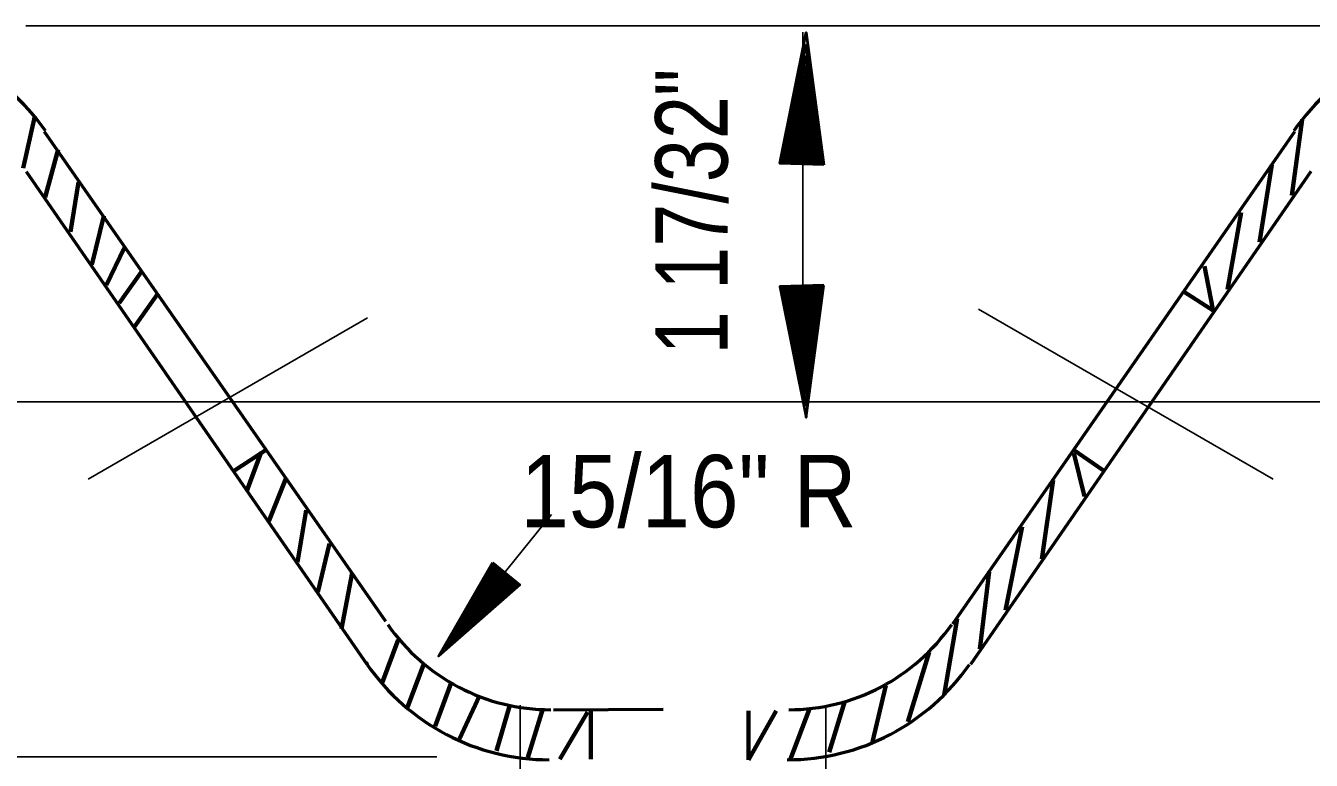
# Model space of a CAD drawing. Extents: x 895.6 to 930.4, y -2278.6 to -2254.7.
# Drawn here: x 901.427 to 903.71, y -2273.45 to -2272.145 of the extents above; entities that cross this region are included whole.
import ezdxf

# ---------------------------------------------------------------- set-up
doc = ezdxf.new("R2010")
doc.units = 0
doc.header["$LTSCALE"] = 0.051
doc.layers.add('1', color=7, linetype='Continuous', lineweight=70)
doc.layers.add('3', color=7, linetype='Continuous', lineweight=40)

msp = doc.modelspace()

# ---------------------------------------------------------------- hatches: boundary and pattern name
at = {"layer": '3'}
for points in [[(902.8445, -2272.3925), (902.7665, -2272.38983), (902.81342, -2272.15717), (902.81342, -2272.15717)], [(902.84058, -2272.39125), (902.77042, -2272.38892), (902.81258, -2272.17958), (902.81258, -2272.17958)], [(902.83708, -2272.39025), (902.774, -2272.38808), (902.812, -2272.19967), (902.812, -2272.19967)], [(902.834, -2272.38925), (902.77725, -2272.38733), (902.81142, -2272.21775), (902.81142, -2272.21775)], [(902.83133, -2272.3885), (902.78017, -2272.38667), (902.81092, -2272.234), (902.81092, -2272.234)], [(902.82867, -2272.3875), (902.78267, -2272.386), (902.81042, -2272.24867), (902.81042, -2272.24867)], [(902.82633, -2272.38692), (902.78492, -2272.38558), (902.80992, -2272.26183), (902.80992, -2272.26183)], [(902.82442, -2272.38617), (902.78708, -2272.38508), (902.80958, -2272.27383), (902.80958, -2272.27383)], [(902.82258, -2272.38583), (902.78892, -2272.3845), (902.80908, -2272.28442), (902.80908, -2272.28442)], [(902.82083, -2272.38517), (902.7905, -2272.38408), (902.80883, -2272.29408), (902.80883, -2272.29408)], [(902.81933, -2272.38467), (902.79217, -2272.38375), (902.8085, -2272.30275), (902.8085, -2272.30275)], [(902.81792, -2272.38433), (902.79358, -2272.38342), (902.80817, -2272.3105), (902.80817, -2272.3105)], [(902.81683, -2272.38383), (902.79475, -2272.38317), (902.808, -2272.31767), (902.808, -2272.31767)], [(902.81567, -2272.38342), (902.79583, -2272.38292), (902.80783, -2272.32375), (902.80783, -2272.32375)], [(902.81475, -2272.38317), (902.79683, -2272.38258), (902.80767, -2272.3295), (902.80767, -2272.3295)], [(902.81383, -2272.38292), (902.79767, -2272.3825), (902.80733, -2272.33458), (902.80733, -2272.33458)], [(902.813, -2272.38267), (902.79842, -2272.38217), (902.80717, -2272.33917), (902.80717, -2272.33917)], [(902.81225, -2272.3825), (902.79925, -2272.38208), (902.80708, -2272.34325), (902.80708, -2272.34325)], [(902.81183, -2272.38217), (902.8, -2272.38192), (902.80708, -2272.34692), (902.80708, -2272.34692)], [(902.81125, -2272.382), (902.80067, -2272.38167), (902.807, -2272.35017), (902.807, -2272.35017)], [(902.81092, -2272.38175), (902.80133, -2272.38142), (902.80717, -2272.35317), (902.80717, -2272.35317)], [(902.81033, -2272.38175), (902.80183, -2272.38142), (902.807, -2272.35592), (902.807, -2272.35592)], [(902.80983, -2272.38158), (902.80225, -2272.38125), (902.80675, -2272.35833), (902.80675, -2272.35833)], [(902.80958, -2272.38142), (902.80275, -2272.38117), (902.80683, -2272.3605), (902.80683, -2272.3605)], [(902.8445, -2272.60583), (902.7665, -2272.6085), (902.81342, -2272.84117), (902.81342, -2272.84117)], [(902.84058, -2272.60708), (902.77042, -2272.60942), (902.81258, -2272.81875), (902.81258, -2272.81875)], [(902.83708, -2272.60808), (902.774, -2272.61025), (902.812, -2272.79867), (902.812, -2272.79867)], [(902.834, -2272.60908), (902.77725, -2272.611), (902.81142, -2272.78058), (902.81142, -2272.78058)], [(902.83133, -2272.60983), (902.78017, -2272.61167), (902.81092, -2272.76433), (902.81092, -2272.76433)], [(902.82867, -2272.61083), (902.78267, -2272.61233), (902.81042, -2272.74967), (902.81042, -2272.74967)], [(902.82633, -2272.61142), (902.78492, -2272.61275), (902.80992, -2272.7365), (902.80992, -2272.7365)], [(902.82442, -2272.61217), (902.78708, -2272.61325), (902.80958, -2272.7245), (902.80958, -2272.7245)], [(902.82258, -2272.6125), (902.78892, -2272.61383), (902.80908, -2272.71392), (902.80908, -2272.71392)], [(902.82083, -2272.61317), (902.7905, -2272.61425), (902.80883, -2272.70425), (902.80883, -2272.70425)], [(902.81933, -2272.61367), (902.79217, -2272.61458), (902.8085, -2272.69558), (902.8085, -2272.69558)], [(902.81792, -2272.614), (902.79358, -2272.61492), (902.80817, -2272.68783), (902.80817, -2272.68783)], [(902.81683, -2272.6145), (902.79475, -2272.61517), (902.808, -2272.68067), (902.808, -2272.68067)], [(902.81567, -2272.61492), (902.79583, -2272.61542), (902.80783, -2272.67458), (902.80783, -2272.67458)], [(902.81475, -2272.61517), (902.79683, -2272.61575), (902.80767, -2272.66883), (902.80767, -2272.66883)], [(902.81383, -2272.61542), (902.79767, -2272.61583), (902.80733, -2272.66375), (902.80733, -2272.66375)], [(902.813, -2272.61567), (902.79842, -2272.61617), (902.80717, -2272.65917), (902.80717, -2272.65917)], [(902.81225, -2272.61583), (902.79925, -2272.61625), (902.80708, -2272.65508), (902.80708, -2272.65508)], [(902.81183, -2272.61617), (902.8, -2272.61642), (902.80708, -2272.65142), (902.80708, -2272.65142)], [(902.81125, -2272.61633), (902.80067, -2272.61667), (902.807, -2272.64817), (902.807, -2272.64817)], [(902.81092, -2272.61658), (902.80133, -2272.61692), (902.80717, -2272.64517), (902.80717, -2272.64517)], [(902.81033, -2272.61658), (902.80183, -2272.61692), (902.807, -2272.64242), (902.807, -2272.64242)], [(902.80983, -2272.61675), (902.80225, -2272.61708), (902.80675, -2272.64), (902.80675, -2272.64)], [(902.80958, -2272.61692), (902.80275, -2272.61717), (902.80683, -2272.63783), (902.80683, -2272.63783)], [(902.25567, -2273.09842), (902.30475, -2273.13808), (902.16, -2273.265), (902.16, -2273.265)], [(902.25817, -2273.10108), (902.30158, -2273.1375), (902.17142, -2273.251), (902.17142, -2273.251)], [(902.25925, -2273.1035), (902.29925, -2273.13575), (902.18183, -2273.23825), (902.18183, -2273.23825)], [(902.26117, -2273.10583), (902.29717, -2273.13483), (902.19117, -2273.22683), (902.19117, -2273.22683)], [(902.26267, -2273.10733), (902.29467, -2273.13375), (902.19942, -2273.21692), (902.19942, -2273.21692)], [(902.26342, -2273.1095), (902.29258, -2273.13317), (902.20683, -2273.20783), (902.20683, -2273.20783)], [(902.26492, -2273.11075), (902.29108, -2273.13183), (902.214, -2273.19975), (902.214, -2273.19975)], [(902.266, -2273.11242), (902.28908, -2273.13183), (902.22008, -2273.19183), (902.22008, -2273.19183)], [(902.26675, -2273.11317), (902.28767, -2273.13075), (902.22533, -2273.1855), (902.22533, -2273.1855)], [(902.26742, -2273.11483), (902.28658, -2273.13), (902.23033, -2273.17933), (902.23033, -2273.17933)], [(902.26833, -2273.11575), (902.28525, -2273.12983), (902.23508, -2273.17383), (902.23508, -2273.17383)], [(902.26892, -2273.11658), (902.28408, -2273.12975), (902.23883, -2273.16892), (902.23883, -2273.16892)], [(902.26967, -2273.1175), (902.28342, -2273.12867), (902.24242, -2273.1645), (902.24242, -2273.1645)], [(902.27025, -2273.11817), (902.28275, -2273.12817), (902.24558, -2273.1605), (902.24558, -2273.1605)], [(902.27067, -2273.11892), (902.28183, -2273.12792), (902.249, -2273.15708), (902.249, -2273.15708)], [(902.27075, -2273.11992), (902.28125, -2273.12775), (902.2515, -2273.15408), (902.2515, -2273.15408)], [(902.27108, -2273.12033), (902.28058, -2273.12792), (902.2535, -2273.15092), (902.2535, -2273.15092)], [(902.27158, -2273.12058), (902.28, -2273.12775), (902.25583, -2273.14875), (902.25583, -2273.14875)], [(902.272, -2273.12133), (902.27925, -2273.12742), (902.25742, -2273.146), (902.25742, -2273.146)], [(902.27225, -2273.12167), (902.2785, -2273.12667), (902.25942, -2273.14375), (902.25942, -2273.14375)], [(902.2725, -2273.12183), (902.27783, -2273.12608), (902.26042, -2273.14192), (902.26042, -2273.14192)], [(902.27283, -2273.12192), (902.27758, -2273.126), (902.26208, -2273.1405), (902.26208, -2273.1405)], [(902.27292, -2273.12217), (902.27733, -2273.12592), (902.26342, -2273.13908), (902.26342, -2273.13908)], [(902.273, -2273.12233), (902.27692, -2273.12583), (902.26425, -2273.1375), (902.26425, -2273.1375)]]:
    msp.add_hatch(color=256, dxfattribs=at).paths.add_polyline_path(points)

# ---------------------------------------------------------------- linework, layer by layer
at = {"layer": '1', "lineweight": 25}
for p, q in [((901.42708, -2272.14508), (903.73033, -2272.14508)), ((902.80742, -2272.15658), (902.80742, -2272.81325)), ((903.6425, -2272.9505), (903.11933, -2272.6485)), ((901.53775, -2272.9505), (902.03392, -2272.66408)), ((900.56375, -2272.81325), (907.81792, -2272.81325)), ((902.23175, -2273.17317), (902.3605, -2273.01342)), ((902.30508, -2273.35175), (902.30508, -2274.17808)), ((902.84783, -2273.35175), (902.84783, -2274.16025)), ((900.40092, -2273.44408), (902.15683, -2273.44408))]:
    msp.add_line(p, q, dxfattribs=at)
at = {"layer": '1'}
for p, q in [((901.4225, -2272.39825), (901.44292, -2272.306)), ((903.67608, -2272.44667), (903.69425, -2272.31142)), ((901.46142, -2272.44958), (901.48442, -2272.36517)), ((903.61833, -2272.5295), (903.64058, -2272.3925)), ((901.5065, -2272.51117), (901.52042, -2272.42325)), ((901.54408, -2272.57), (901.56575, -2272.48267)), ((903.56183, -2272.61358), (903.58575, -2272.47667)), ((901.5705, -2272.60517), (901.60192, -2272.54)), ((901.59308, -2272.63767), (901.63183, -2272.58258)), ((903.5355, -2272.64867), (903.52042, -2272.57225)), ((901.61933, -2272.68042), (901.66192, -2272.62008)), ((903.53783, -2272.65242), (903.48333, -2272.617)), ((901.79775, -2272.93542), (901.854, -2272.89825)), ((901.81975, -2272.97108), (901.84492, -2272.90242)), ((903.34108, -2272.93542), (903.28808, -2272.89825)), ((903.30733, -2272.9815), (903.28883, -2272.90458)), ((901.85892, -2273.02508), (901.88933, -2272.94842)), ((903.232, -2273.09242), (903.252, -2272.95217)), ((901.90933, -2273.09817), (901.92508, -2273.00558)), ((903.1675, -2273.18308), (903.19658, -2273.03542)), ((901.94583, -2273.15142), (901.9665, -2273.06475)), ((901.98792, -2273.21625), (902.0065, -2273.11717)), ((903.12142, -2273.25242), (903.13808, -2273.11542)), ((903.05833, -2273.33375), (903.08133, -2273.19842)), ((902.06008, -2273.31242), (902.08858, -2273.23575)), ((902.99375, -2273.38158), (903.03158, -2273.25808)), ((902.105, -2273.35542), (902.13333, -2273.28042)), ((902.15433, -2273.38925), (902.1825, -2273.3125)), ((902.93075, -2273.41692), (902.95475, -2273.31725)), ((902.19733, -2273.41208), (902.233, -2273.33567)), ((902.26325, -2273.43317), (902.286, -2273.35367)), ((902.31892, -2273.44517), (902.34558, -2273.35875)), ((902.3755, -2273.44792), (902.425, -2273.36467)), ((902.4305, -2273.44792), (902.4305, -2273.362)), ((902.71083, -2273.44917), (902.71075, -2273.362)), ((902.71083, -2273.44917), (902.75992, -2273.362)), ((902.78475, -2273.44917), (902.81933, -2273.35875)), ((902.85383, -2273.43542), (902.88183, -2273.34467))]:
    msp.add_line(p, q, dxfattribs=at)
at = {"layer": '1', "lineweight": 53}
for p, q in [((902.0665, -2273.20358), (901.46025, -2272.3335)), ((903.68042, -2272.3335), (903.07333, -2273.20842)), ((902.03308, -2273.27958), (901.4285, -2272.40467)), ((903.70933, -2272.404), (903.10533, -2273.27958)), ((902.03175, -2273.275), (902.03308, -2273.27958)), ((902.55933, -2273.36), (902.36458, -2273.36075))]:
    msp.add_line(p, q, dxfattribs=at)
for centre, radius, start, end in [((901.13805, -2272.5564), 0.39401, 34.74043, 144.5106), ((904.00339, -2272.5564), 0.39401, 34.74043, 145.25957), ((902.35935, -2273.0079), 0.3523, 214.73767, 270), ((902.7821, -2273.0079), 0.3523, 270, 325.26233), ((902.35689, -2273.05502), 0.39401, 214.73767, 270), ((902.77964, -2273.05502), 0.39401, 270, 325.26233)]:
    msp.add_arc(centre, radius, start, end, dxfattribs=at)
at = {"layer": '3'}
for points in [[(902.8445, -2272.3925), (902.7665, -2272.38983), (902.81342, -2272.15717), (902.81342, -2272.15717)], [(902.84058, -2272.39125), (902.77042, -2272.38892), (902.81258, -2272.17958), (902.81258, -2272.17958)], [(902.83708, -2272.39025), (902.774, -2272.38808), (902.812, -2272.19967), (902.812, -2272.19967)], [(902.834, -2272.38925), (902.77725, -2272.38733), (902.81142, -2272.21775), (902.81142, -2272.21775)], [(902.83133, -2272.3885), (902.78017, -2272.38667), (902.81092, -2272.234), (902.81092, -2272.234)], [(902.82867, -2272.3875), (902.78267, -2272.386), (902.81042, -2272.24867), (902.81042, -2272.24867)], [(902.82633, -2272.38692), (902.78492, -2272.38558), (902.80992, -2272.26183), (902.80992, -2272.26183)], [(902.82442, -2272.38617), (902.78708, -2272.38508), (902.80958, -2272.27383), (902.80958, -2272.27383)], [(902.82258, -2272.38583), (902.78892, -2272.3845), (902.80908, -2272.28442), (902.80908, -2272.28442)], [(902.82083, -2272.38517), (902.7905, -2272.38408), (902.80883, -2272.29408), (902.80883, -2272.29408)], [(902.81933, -2272.38467), (902.79217, -2272.38375), (902.8085, -2272.30275), (902.8085, -2272.30275)], [(902.81792, -2272.38433), (902.79358, -2272.38342), (902.80817, -2272.3105), (902.80817, -2272.3105)], [(902.81683, -2272.38383), (902.79475, -2272.38317), (902.808, -2272.31767), (902.808, -2272.31767)], [(902.81567, -2272.38342), (902.79583, -2272.38292), (902.80783, -2272.32375), (902.80783, -2272.32375)], [(902.81475, -2272.38317), (902.79683, -2272.38258), (902.80767, -2272.3295), (902.80767, -2272.3295)], [(902.81383, -2272.38292), (902.79767, -2272.3825), (902.80733, -2272.33458), (902.80733, -2272.33458)], [(902.813, -2272.38267), (902.79842, -2272.38217), (902.80717, -2272.33917), (902.80717, -2272.33917)], [(902.81225, -2272.3825), (902.79925, -2272.38208), (902.80708, -2272.34325), (902.80708, -2272.34325)], [(902.81183, -2272.38217), (902.8, -2272.38192), (902.80708, -2272.34692), (902.80708, -2272.34692)], [(902.81125, -2272.382), (902.80067, -2272.38167), (902.807, -2272.35017), (902.807, -2272.35017)], [(902.81092, -2272.38175), (902.80133, -2272.38142), (902.80717, -2272.35317), (902.80717, -2272.35317)], [(902.81033, -2272.38175), (902.80183, -2272.38142), (902.807, -2272.35592), (902.807, -2272.35592)], [(902.80983, -2272.38158), (902.80225, -2272.38125), (902.80675, -2272.35833), (902.80675, -2272.35833)], [(902.80958, -2272.38142), (902.80275, -2272.38117), (902.80683, -2272.3605), (902.80683, -2272.3605)], [(902.8445, -2272.60583), (902.7665, -2272.6085), (902.81342, -2272.84117), (902.81342, -2272.84117)], [(902.84058, -2272.60708), (902.77042, -2272.60942), (902.81258, -2272.81875), (902.81258, -2272.81875)], [(902.83708, -2272.60808), (902.774, -2272.61025), (902.812, -2272.79867), (902.812, -2272.79867)], [(902.834, -2272.60908), (902.77725, -2272.611), (902.81142, -2272.78058), (902.81142, -2272.78058)], [(902.83133, -2272.60983), (902.78017, -2272.61167), (902.81092, -2272.76433), (902.81092, -2272.76433)], [(902.82867, -2272.61083), (902.78267, -2272.61233), (902.81042, -2272.74967), (902.81042, -2272.74967)], [(902.82633, -2272.61142), (902.78492, -2272.61275), (902.80992, -2272.7365), (902.80992, -2272.7365)], [(902.82442, -2272.61217), (902.78708, -2272.61325), (902.80958, -2272.7245), (902.80958, -2272.7245)], [(902.82258, -2272.6125), (902.78892, -2272.61383), (902.80908, -2272.71392), (902.80908, -2272.71392)], [(902.82083, -2272.61317), (902.7905, -2272.61425), (902.80883, -2272.70425), (902.80883, -2272.70425)], [(902.81933, -2272.61367), (902.79217, -2272.61458), (902.8085, -2272.69558), (902.8085, -2272.69558)], [(902.81792, -2272.614), (902.79358, -2272.61492), (902.80817, -2272.68783), (902.80817, -2272.68783)], [(902.81683, -2272.6145), (902.79475, -2272.61517), (902.808, -2272.68067), (902.808, -2272.68067)], [(902.81567, -2272.61492), (902.79583, -2272.61542), (902.80783, -2272.67458), (902.80783, -2272.67458)], [(902.81475, -2272.61517), (902.79683, -2272.61575), (902.80767, -2272.66883), (902.80767, -2272.66883)], [(902.81383, -2272.61542), (902.79767, -2272.61583), (902.80733, -2272.66375), (902.80733, -2272.66375)], [(902.813, -2272.61567), (902.79842, -2272.61617), (902.80717, -2272.65917), (902.80717, -2272.65917)], [(902.81225, -2272.61583), (902.79925, -2272.61625), (902.80708, -2272.65508), (902.80708, -2272.65508)], [(902.81183, -2272.61617), (902.8, -2272.61642), (902.80708, -2272.65142), (902.80708, -2272.65142)], [(902.81125, -2272.61633), (902.80067, -2272.61667), (902.807, -2272.64817), (902.807, -2272.64817)], [(902.81092, -2272.61658), (902.80133, -2272.61692), (902.80717, -2272.64517), (902.80717, -2272.64517)], [(902.81033, -2272.61658), (902.80183, -2272.61692), (902.807, -2272.64242), (902.807, -2272.64242)], [(902.80983, -2272.61675), (902.80225, -2272.61708), (902.80675, -2272.64), (902.80675, -2272.64)], [(902.80958, -2272.61692), (902.80275, -2272.61717), (902.80683, -2272.63783), (902.80683, -2272.63783)], [(902.25567, -2273.09842), (902.30475, -2273.13808), (902.16, -2273.265), (902.16, -2273.265)], [(902.25817, -2273.10108), (902.30158, -2273.1375), (902.17142, -2273.251), (902.17142, -2273.251)], [(902.25925, -2273.1035), (902.29925, -2273.13575), (902.18183, -2273.23825), (902.18183, -2273.23825)], [(902.26117, -2273.10583), (902.29717, -2273.13483), (902.19117, -2273.22683), (902.19117, -2273.22683)], [(902.26267, -2273.10733), (902.29467, -2273.13375), (902.19942, -2273.21692), (902.19942, -2273.21692)], [(902.26342, -2273.1095), (902.29258, -2273.13317), (902.20683, -2273.20783), (902.20683, -2273.20783)], [(902.26492, -2273.11075), (902.29108, -2273.13183), (902.214, -2273.19975), (902.214, -2273.19975)], [(902.266, -2273.11242), (902.28908, -2273.13183), (902.22008, -2273.19183), (902.22008, -2273.19183)], [(902.26675, -2273.11317), (902.28767, -2273.13075), (902.22533, -2273.1855), (902.22533, -2273.1855)], [(902.26742, -2273.11483), (902.28658, -2273.13), (902.23033, -2273.17933), (902.23033, -2273.17933)], [(902.26833, -2273.11575), (902.28525, -2273.12983), (902.23508, -2273.17383), (902.23508, -2273.17383)], [(902.26892, -2273.11658), (902.28408, -2273.12975), (902.23883, -2273.16892), (902.23883, -2273.16892)], [(902.26967, -2273.1175), (902.28342, -2273.12867), (902.24242, -2273.1645), (902.24242, -2273.1645)], [(902.27025, -2273.11817), (902.28275, -2273.12817), (902.24558, -2273.1605), (902.24558, -2273.1605)], [(902.27067, -2273.11892), (902.28183, -2273.12792), (902.249, -2273.15708), (902.249, -2273.15708)], [(902.27075, -2273.11992), (902.28125, -2273.12775), (902.2515, -2273.15408), (902.2515, -2273.15408)], [(902.27108, -2273.12033), (902.28058, -2273.12792), (902.2535, -2273.15092), (902.2535, -2273.15092)], [(902.27158, -2273.12058), (902.28, -2273.12775), (902.25583, -2273.14875), (902.25583, -2273.14875)], [(902.272, -2273.12133), (902.27925, -2273.12742), (902.25742, -2273.146), (902.25742, -2273.146)], [(902.27225, -2273.12167), (902.2785, -2273.12667), (902.25942, -2273.14375), (902.25942, -2273.14375)], [(902.2725, -2273.12183), (902.27783, -2273.12608), (902.26042, -2273.14192), (902.26042, -2273.14192)], [(902.27283, -2273.12192), (902.27758, -2273.126), (902.26208, -2273.1405), (902.26208, -2273.1405)], [(902.27292, -2273.12217), (902.27733, -2273.12592), (902.26342, -2273.13908), (902.26342, -2273.13908)], [(902.273, -2273.12233), (902.27692, -2273.12583), (902.26425, -2273.1375), (902.26425, -2273.1375)]]:
    msp.add_lwpolyline(points, close=True, dxfattribs=at)

# ---------------------------------------------------------------- texts
at = {"layer": '1', "width": 0.8}
msp.add_text('1 17/32"', height=0.1286, rotation=90, dxfattribs=at).set_placement((902.67358, -2272.729))
at = {"layer": '1', "width": 0.9}
msp.add_text('15/16" R', height=0.1286, dxfattribs=at).set_placement((902.30567, -2273.03608))

doc.saveas('drawing.dxf')
